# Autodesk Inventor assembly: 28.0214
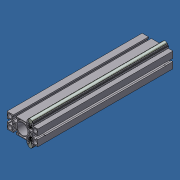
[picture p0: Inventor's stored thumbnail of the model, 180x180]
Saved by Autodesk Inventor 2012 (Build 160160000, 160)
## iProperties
Created: 2011-05
Part Number: 28.0214
Document SubType Name: Assembly
Designer: Administrator
Author: Administrator
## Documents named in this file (4)
- C:\Andys Backup Data\ANDY'S INVENTOR\INVENTOR LIBRARIES\PARTS LIBRARY\READY FOR USE MODULES LG\SUBCOMPONENTS\28.0214 RAIL 45X90H.iam
- C:\Andys Backup Data\ANDY'S INVENTOR\INVENTOR LIBRARIES\PARTS LIBRARY\READY FOR USE MODULES LG\SUBCOMPONENTS\28.0214_1 RAIL 45X90 H PROFILE.ipt
- C:\Andys Backup Data\ANDY'S INVENTOR\INVENTOR LIBRARIES\PARTS LIBRARY\READY FOR USE MODULES LG\SUBCOMPONENTS\28.0215_9 SHAFT SUPP PROF.ipt
- C:\Andys Backup Data\ANDY'S INVENTOR\INVENTOR LIBRARIES\PARTS LIBRARY\READY FOR USE MODULES LG\SUBCOMPONENTS\28.0215_8 SHAFT 12.ipt
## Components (5 placed, 3 different names)
1. 28.0214_1 RAIL 45X90 H PROFILE:1 — Mate:5, Mate:6, Mate:7, Mate:8, Mate:9, Mate:10
2. 28.0215_9 SHAFT SUPP PROF:1 — Mate:2, Mate:4, Mate:5, Mate:10
3. 28.0215_9 SHAFT SUPP PROF:2 — Mate:1, Mate:3, Mate:6, Mate:9
4. 28.0215_8 SHAFT 12:1 — Mate:1, Mate:3, Mate:7
5. 28.0215_8 SHAFT 12:2 — Mate:2, Mate:4, Mate:8
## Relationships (10: Mate 10)
- Mate:1: 28.0215_9 SHAFT SUPP PROF:2 ↔ 28.0215_8 SHAFT 12:1
- Mate:2: 28.0215_9 SHAFT SUPP PROF:1 ↔ 28.0215_8 SHAFT 12:2
- Mate:3: 28.0215_9 SHAFT SUPP PROF:2 ↔ 28.0215_8 SHAFT 12:1
- Mate:4: 28.0215_9 SHAFT SUPP PROF:1 ↔ 28.0215_8 SHAFT 12:2
- Mate:5: 28.0214_1 RAIL 45X90 H PROFILE:1 ↔ 28.0215_9 SHAFT SUPP PROF:1
- Mate:6: 28.0214_1 RAIL 45X90 H PROFILE:1 ↔ 28.0215_9 SHAFT SUPP PROF:2
- Mate:7: 28.0214_1 RAIL 45X90 H PROFILE:1 ↔ 28.0215_8 SHAFT 12:1
- Mate:8: 28.0214_1 RAIL 45X90 H PROFILE:1 ↔ 28.0215_8 SHAFT 12:2
- Mate:9: 28.0214_1 RAIL 45X90 H PROFILE:1 ↔ 28.0215_9 SHAFT SUPP PROF:2
- Mate:10: 28.0214_1 RAIL 45X90 H PROFILE:1 ↔ 28.0215_9 SHAFT SUPP PROF:1
